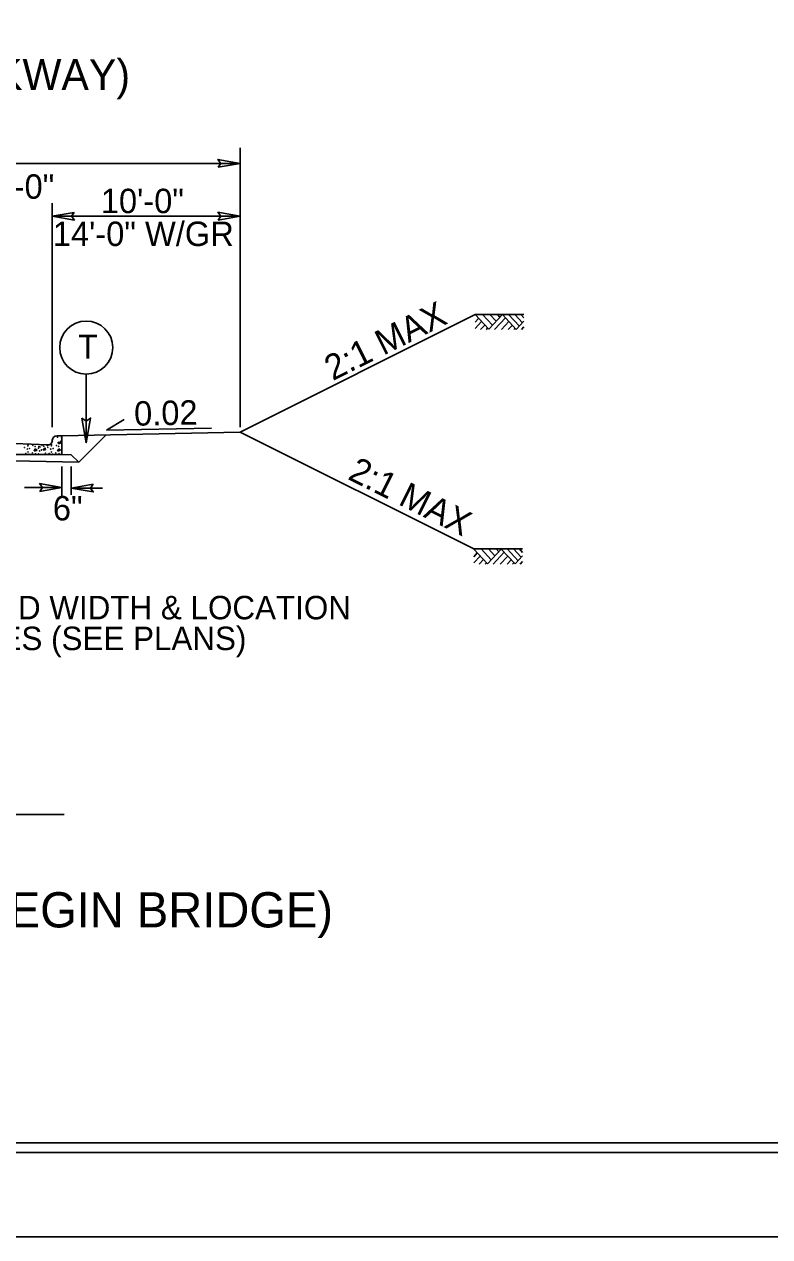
# Model space of a CAD drawing. Extents: x 1904401 to 1905163, y 193929 to 194736.
# Drawn here: x 1904817 to 1904856.7, y 194494.2 to 194558.8 of the extents above; entities that cross this region are included whole.
import ezdxf

# ---------------------------------------------------------------- set-up
doc = ezdxf.new("R2010")
doc.units = 0
for name, color, linetype in [('Old_Level_1', 7, 'Continuous'), ('Old_Level_11', 7, 'Continuous'), ('Old_Level_20', 7, 'Continuous'), ('Prop Dimension Text', 7, 'Continuous'), ('Prop Lane Arrow CELL', 7, 'Continuous'), ('Sheet Cutting Line CELL', 7, 'Continuous'), ('Sheet Plot Border Inside CELL', 7, 'Continuous'), ('Sheet Plot Border Outside CELL', 7, 'Continuous'), ('Sheet Typical CELL', 7, 'Continuous'), ('Typical Arrow Superelevation CELL', 7, 'Continuous'), ('Typical Berm CELL', 7, 'Continuous'), ('Typical Curb CELL', 7, 'Continuous'), ('Typical Hinge Slope Arterial CELL', 7, 'Continuous'), ('Typical Pavement Slope CELL', 7, 'Continuous'), ('Typical Terminator CELL', 7, 'Continuous'), ('Typical Text Centerline CELL', 7, 'Continuous')]:
    doc.layers.add(name, color=color, linetype=linetype)

msp = doc.modelspace()

# ---------------------------------------------------------------- linework, layer by layer
at = {"layer": 'Old_Level_1'}
for p, q in [((1904765, 194551.344), (1904828.5, 194551.344)), ((1904828.5, 194548.532), (1904818.5, 194548.532)), ((1904841.02, 194543.292), (1904841.744, 194542.513)), ((1904841.02, 194542.891), (1904841.206, 194543.091)), ((1904841.412, 194543.3), (1904841.944, 194542.727)), ((1904841.744, 194542.513), (1904842.475, 194543.299)), ((1904841.81, 194543.3), (1904842.143, 194542.941)), ((1904842.054, 194542.495), (1904842.641, 194543.123)), ((1904842.211, 194543.3), (1904842.345, 194543.157)), ((1904842.475, 194543.299), (1904843.216, 194542.503)), ((1904842.797, 194543.3), (1904843.378, 194542.677)), ((1904843.13, 194543.3), (1904843.545, 194542.856)), ((1904843.451, 194543.3), (1904843.621, 194543.117)), ((1904841.02, 194542.558), (1904841.363, 194542.924)), ((1904841.309, 194542.495), (1904841.535, 194542.738)), ((1904841.619, 194542.495), (1904841.691, 194542.571)), ((1904842.425, 194542.495), (1904842.825, 194542.924)), ((1904842.791, 194542.495), (1904843.008, 194542.728)), ((1904843.085, 194542.495), (1904843.155, 194542.569)), ((1904843.216, 194542.503), (1904843.62, 194542.938)), ((1904843.486, 194542.495), (1904843.621, 194542.638)), ((1904840.953, 194530.806), (1904841.677, 194530.027)), ((1904841.344, 194530.814), (1904841.877, 194530.241)), ((1904841.677, 194530.027), (1904842.408, 194530.813)), ((1904841.742, 194530.814), (1904842.075, 194530.455)), ((1904842.144, 194530.814), (1904842.277, 194530.671)), ((1904842.408, 194530.813), (1904843.149, 194530.017)), ((1904842.73, 194530.814), (1904843.31, 194530.191)), ((1904843.063, 194530.814), (1904843.477, 194530.37)), ((1904843.383, 194530.814), (1904843.553, 194530.631)), ((1904840.953, 194530.405), (1904841.139, 194530.605)), ((1904840.953, 194530.072), (1904841.295, 194530.438)), ((1904841.241, 194530.009), (1904841.468, 194530.252)), ((1904841.987, 194530.009), (1904842.573, 194530.637)), ((1904842.357, 194530.009), (1904842.757, 194530.438)), ((1904842.723, 194530.009), (1904842.94, 194530.242)), ((1904843.149, 194530.017), (1904843.553, 194530.452)), ((1904843.419, 194530.009), (1904843.553, 194530.152)), ((1904841.552, 194530.009), (1904841.623, 194530.085)), ((1904843.018, 194530.009), (1904843.087, 194530.083)), ((1904766.738, 194516.676), (1904819.131, 194516.676))]:
    msp.add_line(p, q, dxfattribs=at)
for points in [[(1904841.02, 194543.3), (1904843.62, 194543.3)], [(1904840.953, 194530.814), (1904843.553, 194530.814)]]:
    msp.add_lwpolyline(points, dxfattribs=at)
at = {"layer": 'Old_Level_11'}
msp.add_line((1904820.305, 194540.124), (1904820.305, 194536.47), dxfattribs=at)
msp.add_lwpolyline([(1904820.079, 194537.779), (1904820.305, 194536.47), (1904820.538, 194537.786), (1904820.305, 194537.619)], close=True, dxfattribs=at)
msp.add_circle((1904820.305, 194541.538), 1.414, dxfattribs=at)
at = {"layer": 'Prop Dimension Text'}
for p, q in [((1904828.5, 194552.172), (1904828.5, 194537.306)), ((1904818.5, 194549.225), (1904818.5, 194537.306))]:
    msp.add_line(p, q, dxfattribs=at)
at = {"layer": 'Prop Lane Arrow CELL'}
for p, q in [((1904819, 194535.202), (1904819, 194533.663)), ((1904819.5, 194535.201), (1904819.5, 194533.703)), ((1904819, 194534.085), (1904817.01, 194534.085)), ((1904821.172, 194534.057), (1904819.5, 194534.057))]:
    msp.add_line(p, q, dxfattribs=at)
at = {"layer": 'Sheet Cutting Line CELL'}
msp.add_line((1904710.692, 194494.195), (1905047.492, 194494.195), dxfattribs=at)
at = {"layer": 'Sheet Plot Border Inside CELL'}
msp.add_lwpolyline([(1905046.592, 194709.705), (1904713.292, 194709.705), (1904713.292, 194498.685), (1905046.592, 194498.685)], close=True, dxfattribs=at)
at = {"layer": 'Sheet Plot Border Outside CELL'}
msp.add_lwpolyline([(1905047.492, 194714.195), (1904710.692, 194714.195), (1904710.692, 194494.195), (1905047.492, 194494.195)], close=True, dxfattribs=at)
at = {"layer": 'Sheet Typical CELL'}
msp.add_lwpolyline([(1905044.092, 194709.195), (1904744.092, 194709.195), (1904744.092, 194499.195), (1905044.092, 194499.195)], close=True, dxfattribs=at)
at = {"layer": 'Typical Arrow Superelevation CELL'}
for q in [(1904822.334, 194537.705), (1904826.987, 194537.249)]:
    msp.add_line((1904821.394, 194537.137), q, dxfattribs=at)
at = {"layer": 'Typical Berm CELL'}
msp.add_line((1904828.5, 194537.04), (1904819, 194536.842), dxfattribs=at)
at = {"layer": 'Typical Curb CELL'}
for p, q in [((1904818.5, 194536.592), (1904818.5, 194536.603)), ((1904819, 194536.842), (1904818.74, 194536.842)), ((1904819, 194535.842), (1904819, 194536.842)), ((1904816.5, 194536.426), (1904818.251, 194536.353)), ((1904817.526, 194536.031), (1904817.589, 194536.145)), ((1904817.692, 194536.07), (1904817.526, 194536.031)), ((1904817.589, 194536.145), (1904817.692, 194536.07)), ((1904818.011, 194536.082), (1904818.096, 194536.202)), ((1904818.13, 194536.088), (1904818.011, 194536.082)), ((1904818.096, 194536.202), (1904818.13, 194536.088)), ((1904818.775, 194536.031), (1904818.838, 194536.145)), ((1904818.941, 194536.07), (1904818.775, 194536.031)), ((1904818.809, 194536.509), (1904818.826, 194536.418)), ((1904818.964, 194536.464), (1904818.809, 194536.509)), ((1904818.826, 194536.418), (1904818.964, 194536.464)), ((1904818.838, 194536.145), (1904818.941, 194536.07)), ((1904819, 194535.842), (1904816.5, 194535.842))]:
    msp.add_line(p, q, dxfattribs=at)
for centre in [(1904818.77, 194536.766), (1904818.987, 194536.732), (1904817.018, 194536.219), (1904817.167, 194536.134), (1904817.195, 194536.305), (1904817.201, 194535.98), (1904817.212, 194536.355), (1904817.292, 194536.162), (1904817.435, 194535.928), (1904817.469, 194536.327), (1904817.589, 194536.276), (1904817.766, 194536.179), (1904817.783, 194536.276), (1904817.823, 194536.037), (1904817.839, 194536.242), (1904817.919, 194536.082), (1904817.948, 194536.336), (1904818.045, 194536.282), (1904818.239, 194536.321), (1904818.267, 194536.219), (1904818.416, 194536.134), (1904818.444, 194536.305), (1904818.45, 194535.98), (1904818.461, 194536.355), (1904818.541, 194536.162), (1904818.684, 194535.928), (1904818.718, 194536.327), (1904818.838, 194536.276), (1904818.935, 194536.549), (1904817.087, 194535.894), (1904817.258, 194535.865), (1904817.606, 194535.888), (1904817.76, 194535.871), (1904817.971, 194535.848), (1904818.13, 194535.917), (1904818.336, 194535.894), (1904818.507, 194535.865), (1904818.855, 194535.888)]:
    msp.add_circle(centre, 0.00802, dxfattribs=at)
for centre, start, end in [((1904818.261, 194536.592), 267.61554, 0), ((1904818.74, 194536.603), 90, 180)]:
    msp.add_arc(centre, 0.24, start, end, dxfattribs=at)
at = {"layer": 'Typical Hinge Slope Arterial CELL'}
for p in [(1904841.02, 194543.3), (1904840.953, 194530.814)]:
    msp.add_line(p, (1904828.5, 194537.04), dxfattribs=at)
at = {"layer": 'Typical Pavement Slope CELL'}
for p, q in [((1904819.904, 194535.429), (1904821.367, 194536.891)), ((1904819.904, 194535.429), (1904796.75, 194535.974)), ((1904819.5, 194535.832), (1904819, 194535.842)), ((1904819.904, 194535.429), (1904819.5, 194535.832))]:
    msp.add_line(p, q, dxfattribs=at)
at = {"layer": 'Typical Terminator CELL'}
for points in [[(1904827.329, 194551.143), (1904828.5, 194551.344), (1904827.322, 194551.553), (1904827.472, 194551.344)], [(1904819.672, 194548.734), (1904818.5, 194548.532), (1904819.679, 194548.324), (1904819.529, 194548.532)], [(1904827.329, 194548.33), (1904828.5, 194548.532), (1904827.322, 194548.74), (1904827.472, 194548.532)], [(1904817.828, 194533.883), (1904819, 194534.085), (1904817.822, 194534.293), (1904817.972, 194534.085)], [(1904820.672, 194534.259), (1904819.5, 194534.057), (1904820.678, 194533.849), (1904820.528, 194534.057)]]:
    msp.add_lwpolyline(points, close=True, dxfattribs=at)

# ---------------------------------------------------------------- texts
at = {"layer": 'Old_Level_1'}
for s, p in [('2\'-0"', (1904815.143, 194549.462)), ('10\'-0" ', (1904821.082, 194548.695)), ('14\'-0" W/GR', (1904818.525, 194546.945))]:
    msp.add_text(s, height=1.3, dxfattribs=at).set_placement(p)
at = {"layer": 'Old_Level_20'}
msp.add_text('T', height=1.279, dxfattribs=at).set_placement((1904819.876, 194540.941))
at = {"layer": 'Prop Dimension Text'}
msp.add_text('0.02', height=1.3, rotation=1.1462, dxfattribs=at).set_placement((1904822.868, 194537.375))
at = {"layer": 'Prop Lane Arrow CELL'}
msp.add_text('6"', height=1.3, rotation=0.00016, dxfattribs=at).set_placement((1904818.528, 194532.338))
for s, height, p in [('ISLAND WIDTH & LOCATION', 1.25, (1904811.839, 194527.069)), ('VARIES (SEE PLANS)', 1.25, (1904811.839, 194525.43)), ('-L- STA. 28+87.00 TO 31+71.00 (BEGIN BRIDGE)', 1.875, (1904777.014, 194510.665))]:
    msp.add_text(s, height=height, dxfattribs=at).set_placement(p)
at = {"layer": 'Typical Hinge Slope Arterial CELL'}
for rotation, p in [(26.56505, (1904833.436, 194539.747)), (333.43495, (1904834.181, 194534.56))]:
    msp.add_text('2:1 MAX', height=1.35, rotation=rotation, dxfattribs=at).set_placement(p)
at = {"layer": 'Typical Text Centerline CELL'}
msp.add_text('L -L- (FORUM PARKWAY)', height=1.64109, rotation=359.9469, dxfattribs=at).set_placement((1904796.428, 194555.275))

doc.saveas('drawing.dxf')
